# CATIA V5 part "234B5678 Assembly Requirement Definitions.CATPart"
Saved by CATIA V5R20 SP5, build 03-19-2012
Part number: 234B5678 Assembly Requirement Definitions
Bounding box of the stored display mesh (mm): x 31600.748 to 31913.246, y -11341 to -11182.372, z 5290.673 to 5420.639
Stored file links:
  C:\Users\rem1927\Desktop\Current Explicit Composite Demo\234B5678 Assembly Requirement Definitions.CATPart
  C:\Users\rem1927\Desktop\Current Explicit Composite Demo\234B5678-1 Composite Product.CATProduct
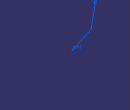
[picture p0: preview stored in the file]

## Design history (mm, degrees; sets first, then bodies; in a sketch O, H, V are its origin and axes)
Parameters
  Material = "Nylon Thread # 3a"
  Stitches_Per_Inch = 12
WSupportSet1
Set1
  Plane1: type Offset, RefPlane Plane5, Offset 12.7
  Plane2: type Offset, RefPlane Plane1, Offset 27.94
  Plane3: type Offset, RefPlane Plane6, Offset 203.2
  Split1: ToCut DatumSurface2, Cutting (Plane3; DatumSurface3; DatumSurface4; Plane5)
  Intersect1: ToIntersect1 Plane1, ToIntersect2 Split1
  Intersect2: ToIntersect1 Plane2, ToIntersect2 Split1
Set2 "Stitching"
  Sweep1 "Stitch 1": type Segment, GuideCrv Intersect1, GuideSurf Split1, Length1 12.7, Length2 7.62, Angle 90
  Sweep2 "Stitch 2": type Segment, GuideCrv Intersect2, GuideSurf Split1, Length1 12.7, Length2 7.62, Angle 90
Set3 "No Splice Zone"
  DatumSurface1
  Plane4: type Offset, RefPlane DatumSurface1, Offset 0
  Sketch1 on Plane4, origin (6152.1168, -19621.3378, 2981.3392), H (0.9542, 0.2992, 0), V (-0.0429, 0.1369, 0.9897)
    line L1 (26901.2235, 2460.2011) -> (27095.8246, 2427.9461)
    line L2 (27095.8246, 2427.9461) -> (27095.8246, 2399.6246)
    line L3 (27095.8246, 2399.6246) -> (26901.2235, 2387.8239)
    line L4 (26901.2235, 2387.8239) -> (26901.2235, 2460.2011)
    vertical: L2 V, L4 V
  Extrude1: Lim1 31.75, Lim2 0, Element1 Sketch1
Set4
  Plane5 "EOP Flange": linked copy from another document
  Plane6 "reference_plane": linked copy from another document
  DatumSurface2 "Core Layup Surface": linked copy from another document
  DatumSurface3 "aft_trim_surface": linked copy from another document
  DatumSurface4 "fwd_trim_surface": linked copy from another document
Body1 (main body)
